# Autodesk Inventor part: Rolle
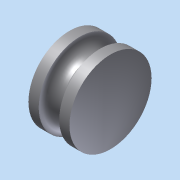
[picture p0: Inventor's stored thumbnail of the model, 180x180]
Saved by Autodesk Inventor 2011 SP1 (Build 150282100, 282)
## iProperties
Created: 2011-01
Part Number: Rolle
Document SubType Name: Modeling
Designer: Fertigung
Density: 1 g/cm^3
Author: Fertigung
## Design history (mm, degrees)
sketch "Skizze1"
  geometry: L1 (0, 24.6)-(0, -4.1) reference; L2 (-4, 0)-(24, 0) reference; L3 (0, 0)-(0, 20); L4 (0, 20)-(5, 20); L5 (0, 0)-(20, 0); L6 (20, 0)-(20, 20); L7 (20, 20)-(15, 20); L8 (10.96, 19.308)-(9.04, 19.308); L9 (10, 17)-(10, 13.386); C1 r 3.5 at (10, 17); A1 r 6 centre (10.96, 19.308) between (5, 20) and (10, 13.386); A2 r 6 centre (9.04, 19.308) between (10, 13.386) and (15, 20)
  constraints: 14 end point, 4 point on circle, 3 centre point, 3 perpendicular, 2 point on line, 1 collinear, 1 equal radius, 1 horizontal, 1 tangent, 1 vertical
  dimensions: "d0" = 20 distance of L3.start L3.end; "d1" = 5 distance of L3.end L4.end; "d5" = 7 diameter of C1; "d6" = 6 radius of A1; "d7" = 10 distance of L4.end L7.end; "d8" = 3 distance from line of L4 L9.start; "d9" = 20 distance between parallel lines of L1 L6
revolve "Umdrehung1" sketch "Skizze1" stored, may be unused: angle "d10" = 90 deg
node "Volumenkörper1"
